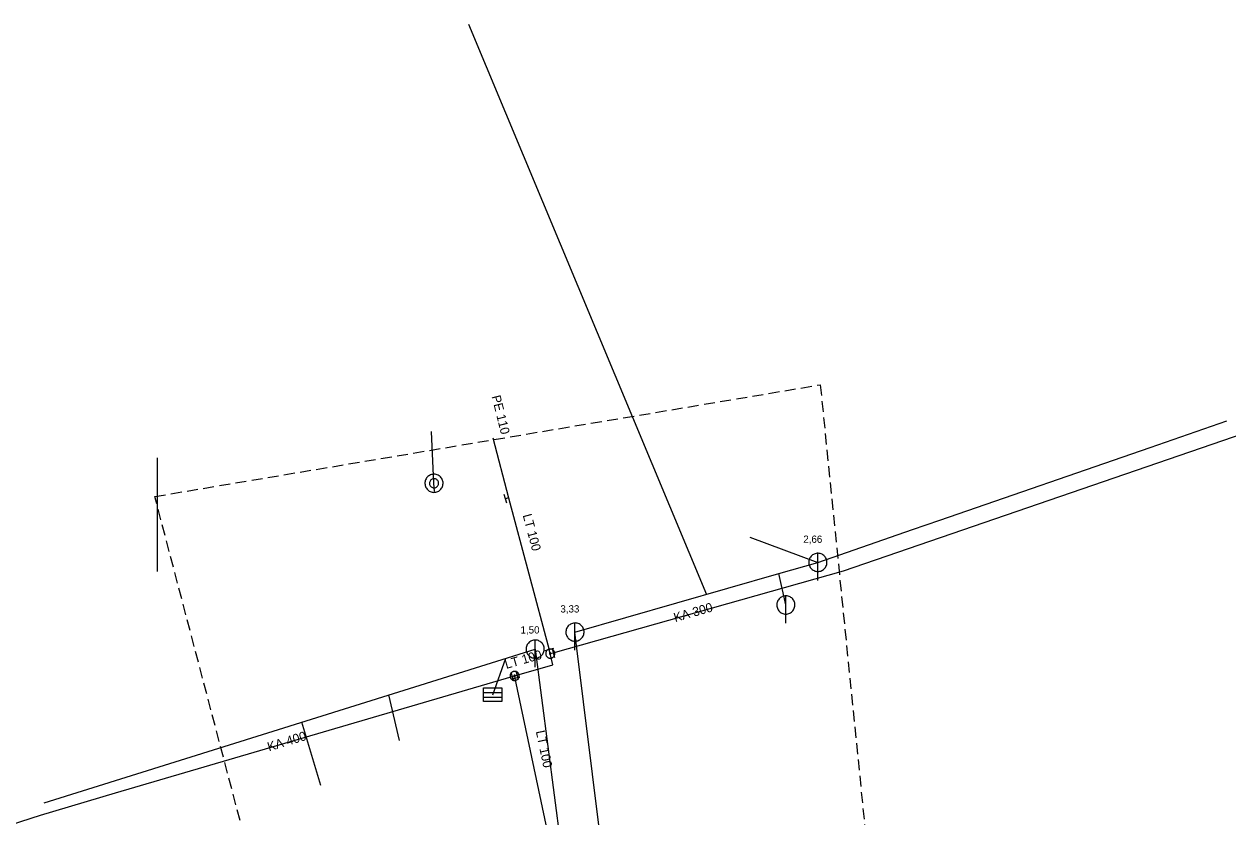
# Model space of a CAD drawing. Extents: x -689820 to -689363, y -975369 to -975062.
# Drawn here: x -689676.5 to -689544.2, y -975149.6 to -975062.5 of the extents above; entities that cross this region are included whole.
import ezdxf

# ---------------------------------------------------------------- set-up
doc = ezdxf.new("R2010")
doc.units = 0
doc.header["$LTSCALE"] = 0.4
doc.linetypes.add('MEDIUM_DASHED', pattern=[4.5, 3, -1.5])
doc.layers.add('1', color=7, linetype='Continuous')
for name, color, linetype, lineweight in [('11', 7, 'Continuous', 13), ('14', 7, 'Continuous', 25), ('17', 7, 'Continuous', 25), ('22', 7, 'Continuous', 13), ('34', 7, 'Continuous', 13), ('47', 7, 'Continuous', 13), ('63', 7, 'MEDIUM_DASHED', 25)]:
    doc.layers.add(name, color=color, linetype=linetype, lineweight=lineweight)

msp = doc.modelspace()

# ---------------------------------------------------------------- linework, layer by layer
at = {"layer": '11'}
for p, q in [((-689627.632, -975062.464), (-689601.514, -975125.167)), ((-689631.44, -975112.952), (-689631.719, -975107.264)), ((-689661.83, -975122.655), (-689661.83, -975110.164)), ((-689631.384, -975113.844), (-689631.44, -975112.952)), ((-689596.725, -975118.868), (-689589.26, -975121.649)), ((-689592.78, -975126.329), (-689593.565, -975122.886)), ((-689624.972, -975136.205), (-689623.543, -975132.188)), ((-689635.232, -975141.223), (-689636.395, -975136.218)), ((-689643.875, -975146.186), (-689645.974, -975139.223))]:
    msp.add_line(p, q, dxfattribs=at)
at = {"layer": '14', "lineweight": 13}
for p, q in [((-689623.257, -975114.555), (-689623.579, -975114.66)), ((-689618.668, -975131.679), (-689618.789, -975131.26)), ((-689618.668, -975131.679), (-689618.329, -975131.609)), ((-689622.587, -975134.128), (-689622.51, -975134.399))]:
    msp.add_line(p, q, dxfattribs=at)
at = {"layer": '14'}
for p, q in [((-689609.76, -975179.3), (-689615.949, -975129.309)), ((-689674.28, -975148.101), (-689620.329, -975131.18)), ((-689620.329, -975131.18), (-689613.954, -975179.785))]:
    msp.add_line(p, q, dxfattribs=at)
for points in [[(-689589.26, -975121.649), (-689578.848, -975118.046), (-689575.848, -975117.009), (-689552.767, -975109.022), (-689544.32, -975106.1)], [(-689615.949, -975129.309), (-689593.565, -975122.886), (-689589.26, -975121.649)]]:
    msp.add_lwpolyline(points, dxfattribs=at)
at = {"layer": '14', "lineweight": 13}
msp.add_lwpolyline([(-689622.85, -975134.205), (-689622.587, -975134.128), (-689622.32, -975134.05)], dxfattribs=at)
at = {"layer": '17'}
for points in [[(-689618.329, -975131.609), (-689586.448, -975122.573), (-689510.214, -975096.362), (-689500.742, -975093.538)], [(-689624.98, -975107.969), (-689623.257, -975114.555), (-689618.789, -975131.26)], [(-689622.32, -975134.05), (-689618.366, -975132.898), (-689618.668, -975131.679)], [(-689742.145, -975169.096), (-689736.511, -975167.526), (-689719.508, -975163.375), (-689716.769, -975162.653), (-689711.482, -975161.26), (-689710.52, -975160.971), (-689674.675, -975149.452), (-689666.449, -975146.987), (-689622.85, -975134.205)], [(-689614.585, -975177.62), (-689615.184, -975174.495), (-689618.58, -975153.313), (-689618.739, -975152.34), (-689619, -975151.02), (-689622.51, -975134.399)]]:
    msp.add_lwpolyline(points, dxfattribs=at)
at = {"layer": '22'}
for p, q in [((-689589.26, -975123.649), (-689589.259, -975120.649)), ((-689592.78, -975128.329), (-689592.779, -975125.329)), ((-689615.949, -975131.309), (-689615.948, -975128.309)), ((-689620.329, -975133.18), (-689620.328, -975130.18)), ((-689625.983, -975135.948), (-689623.983, -975135.948)), ((-689625.983, -975136.448), (-689623.983, -975136.448))]:
    msp.add_line(p, q, dxfattribs=at)
for points in [[(-689630.44, -975112.952), (-689630.446, -975112.843), (-689630.463, -975112.735), (-689630.494, -975112.629), (-689630.534, -975112.528), (-689630.585, -975112.431), (-689630.647, -975112.341), (-689630.72, -975112.258), (-689630.799, -975112.184), (-689630.887, -975112.118), (-689630.982, -975112.063), (-689631.081, -975112.018), (-689631.186, -975111.985), (-689631.294, -975111.963), (-689631.402, -975111.953), (-689631.512, -975111.955), (-689631.62, -975111.969), (-689631.727, -975111.994), (-689631.83, -975112.031), (-689631.928, -975112.08), (-689632.021, -975112.138), (-689632.107, -975112.207), (-689632.183, -975112.284), (-689632.252, -975112.37), (-689632.311, -975112.462), (-689632.36, -975112.56), (-689632.397, -975112.663), (-689632.423, -975112.77), (-689632.436, -975112.878), (-689632.438, -975112.988), (-689632.428, -975113.097), (-689632.407, -975113.204), (-689632.374, -975113.308), (-689632.33, -975113.408), (-689632.274, -975113.503), (-689632.208, -975113.591), (-689632.134, -975113.671), (-689632.051, -975113.743), (-689631.962, -975113.805), (-689631.865, -975113.857), (-689631.764, -975113.898), (-689631.659, -975113.928), (-689631.551, -975113.946), (-689631.441, -975113.952), (-689631.331, -975113.946), (-689631.223, -975113.928), (-689631.119, -975113.899), (-689631.017, -975113.858), (-689630.919, -975113.806), (-689630.83, -975113.744), (-689630.747, -975113.673), (-689630.671, -975113.593), (-689630.607, -975113.505), (-689630.551, -975113.411), (-689630.507, -975113.311), (-689630.473, -975113.207), (-689630.451, -975113.099), (-689630.441, -975112.99)], [(-689630.94, -975112.952), (-689630.946, -975112.875), (-689630.963, -975112.8), (-689630.992, -975112.728), (-689631.032, -975112.662), (-689631.083, -975112.602), (-689631.141, -975112.551), (-689631.205, -975112.51), (-689631.277, -975112.479), (-689631.352, -975112.46), (-689631.428, -975112.452), (-689631.507, -975112.456), (-689631.581, -975112.473), (-689631.654, -975112.5), (-689631.722, -975112.539), (-689631.781, -975112.587), (-689631.833, -975112.645), (-689631.877, -975112.709), (-689631.909, -975112.779), (-689631.929, -975112.854), (-689631.94, -975112.931), (-689631.936, -975113.008), (-689631.921, -975113.084), (-689631.896, -975113.157), (-689631.858, -975113.225), (-689631.811, -975113.286), (-689631.755, -975113.34), (-689631.691, -975113.384), (-689631.622, -975113.418), (-689631.548, -975113.44), (-689631.472, -975113.451), (-689631.394, -975113.45), (-689631.318, -975113.437), (-689631.245, -975113.412), (-689631.176, -975113.377), (-689631.114, -975113.331), (-689631.058, -975113.276), (-689631.014, -975113.213), (-689630.977, -975113.144), (-689630.953, -975113.071), (-689630.941, -975112.994)], [(-689588.26, -975121.649), (-689588.265, -975121.54), (-689588.283, -975121.432), (-689588.313, -975121.326), (-689588.353, -975121.225), (-689588.405, -975121.128), (-689588.467, -975121.038), (-689588.539, -975120.955), (-689588.619, -975120.881), (-689588.707, -975120.815), (-689588.801, -975120.76), (-689588.901, -975120.715), (-689589.006, -975120.682), (-689589.113, -975120.66), (-689589.222, -975120.65), (-689589.332, -975120.652), (-689589.44, -975120.666), (-689589.547, -975120.691), (-689589.65, -975120.728), (-689589.748, -975120.777), (-689589.84, -975120.835), (-689589.926, -975120.904), (-689590.003, -975120.981), (-689590.072, -975121.067), (-689590.131, -975121.159), (-689590.179, -975121.257), (-689590.216, -975121.36), (-689590.242, -975121.467), (-689590.256, -975121.575), (-689590.259, -975121.685), (-689590.249, -975121.794), (-689590.228, -975121.901), (-689590.194, -975122.005), (-689590.15, -975122.105), (-689590.095, -975122.2), (-689590.029, -975122.288), (-689589.955, -975122.368), (-689589.872, -975122.44), (-689589.782, -975122.502), (-689589.686, -975122.554), (-689589.584, -975122.595), (-689589.479, -975122.625), (-689589.371, -975122.643), (-689589.261, -975122.649), (-689589.152, -975122.643), (-689589.044, -975122.625), (-689588.939, -975122.596), (-689588.837, -975122.555), (-689588.74, -975122.503), (-689588.65, -975122.441), (-689588.567, -975122.37), (-689588.492, -975122.29), (-689588.427, -975122.202), (-689588.371, -975122.108), (-689588.327, -975122.008), (-689588.293, -975121.904), (-689588.271, -975121.796), (-689588.261, -975121.687)], [(-689591.78, -975126.329), (-689591.785, -975126.22), (-689591.803, -975126.112), (-689591.833, -975126.006), (-689591.873, -975125.905), (-689591.925, -975125.808), (-689591.987, -975125.718), (-689592.059, -975125.635), (-689592.139, -975125.561), (-689592.227, -975125.495), (-689592.321, -975125.44), (-689592.421, -975125.395), (-689592.526, -975125.362), (-689592.633, -975125.34), (-689592.742, -975125.33), (-689592.852, -975125.332), (-689592.96, -975125.346), (-689593.067, -975125.371), (-689593.17, -975125.408), (-689593.268, -975125.457), (-689593.36, -975125.515), (-689593.446, -975125.584), (-689593.523, -975125.661), (-689593.592, -975125.747), (-689593.651, -975125.839), (-689593.699, -975125.937), (-689593.736, -975126.04), (-689593.762, -975126.147), (-689593.776, -975126.255), (-689593.779, -975126.365), (-689593.769, -975126.474), (-689593.748, -975126.581), (-689593.714, -975126.685), (-689593.67, -975126.785), (-689593.615, -975126.88), (-689593.549, -975126.968), (-689593.475, -975127.048), (-689593.392, -975127.12), (-689593.302, -975127.182), (-689593.206, -975127.234), (-689593.104, -975127.275), (-689592.999, -975127.305), (-689592.891, -975127.323), (-689592.781, -975127.329), (-689592.672, -975127.323), (-689592.564, -975127.305), (-689592.459, -975127.276), (-689592.357, -975127.235), (-689592.26, -975127.183), (-689592.17, -975127.121), (-689592.087, -975127.05), (-689592.012, -975126.97), (-689591.947, -975126.882), (-689591.891, -975126.788), (-689591.847, -975126.688), (-689591.813, -975126.584), (-689591.791, -975126.476), (-689591.781, -975126.367)], [(-689614.949, -975129.309), (-689614.954, -975129.2), (-689614.972, -975129.092), (-689615.002, -975128.986), (-689615.042, -975128.885), (-689615.094, -975128.788), (-689615.156, -975128.698), (-689615.228, -975128.615), (-689615.308, -975128.541), (-689615.396, -975128.475), (-689615.49, -975128.42), (-689615.59, -975128.375), (-689615.695, -975128.342), (-689615.802, -975128.32), (-689615.911, -975128.31), (-689616.021, -975128.312), (-689616.129, -975128.326), (-689616.236, -975128.351), (-689616.339, -975128.388), (-689616.437, -975128.437), (-689616.529, -975128.495), (-689616.615, -975128.564), (-689616.692, -975128.641), (-689616.761, -975128.727), (-689616.82, -975128.819), (-689616.868, -975128.917), (-689616.905, -975129.02), (-689616.931, -975129.127), (-689616.945, -975129.235), (-689616.948, -975129.345), (-689616.938, -975129.454), (-689616.917, -975129.561), (-689616.883, -975129.665), (-689616.839, -975129.765), (-689616.784, -975129.86), (-689616.718, -975129.948), (-689616.644, -975130.028), (-689616.561, -975130.1), (-689616.471, -975130.162), (-689616.375, -975130.214), (-689616.273, -975130.255), (-689616.168, -975130.285), (-689616.06, -975130.303), (-689615.95, -975130.309), (-689615.841, -975130.303), (-689615.733, -975130.285), (-689615.628, -975130.256), (-689615.526, -975130.215), (-689615.429, -975130.163), (-689615.339, -975130.101), (-689615.256, -975130.03), (-689615.181, -975129.95), (-689615.116, -975129.862), (-689615.06, -975129.768), (-689615.016, -975129.668), (-689614.982, -975129.564), (-689614.96, -975129.456), (-689614.95, -975129.347)], [(-689619.329, -975131.18), (-689619.334, -975131.071), (-689619.352, -975130.963), (-689619.382, -975130.857), (-689619.422, -975130.756), (-689619.474, -975130.659), (-689619.536, -975130.569), (-689619.608, -975130.486), (-689619.688, -975130.412), (-689619.776, -975130.346), (-689619.87, -975130.291), (-689619.97, -975130.246), (-689620.075, -975130.213), (-689620.182, -975130.191), (-689620.291, -975130.181), (-689620.401, -975130.183), (-689620.509, -975130.197), (-689620.616, -975130.222), (-689620.719, -975130.259), (-689620.817, -975130.308), (-689620.909, -975130.366), (-689620.995, -975130.435), (-689621.072, -975130.512), (-689621.141, -975130.598), (-689621.2, -975130.69), (-689621.248, -975130.788), (-689621.285, -975130.891), (-689621.311, -975130.998), (-689621.325, -975131.106), (-689621.328, -975131.216), (-689621.318, -975131.325), (-689621.297, -975131.432), (-689621.263, -975131.536), (-689621.219, -975131.636), (-689621.164, -975131.731), (-689621.098, -975131.819), (-689621.024, -975131.899), (-689620.941, -975131.971), (-689620.851, -975132.033), (-689620.755, -975132.085), (-689620.653, -975132.126), (-689620.548, -975132.156), (-689620.44, -975132.174), (-689620.33, -975132.18), (-689620.221, -975132.174), (-689620.113, -975132.156), (-689620.008, -975132.127), (-689619.906, -975132.086), (-689619.809, -975132.034), (-689619.719, -975131.972), (-689619.636, -975131.901), (-689619.561, -975131.821), (-689619.496, -975131.733), (-689619.44, -975131.639), (-689619.396, -975131.539), (-689619.362, -975131.435), (-689619.34, -975131.327), (-689619.33, -975131.218)], [(-689625.983, -975135.448), (-689623.983, -975135.448), (-689623.983, -975136.948), (-689625.983, -975136.948)]]:
    msp.add_lwpolyline(points, close=True, dxfattribs=at)
at = {"layer": '34'}
for p, q in [((-689623.423, -975115.135), (-689623.733, -975114.184)), ((-689618.306, -975131.13), (-689619.272, -975131.388)), ((-689618.465, -975131.128), (-689618.193, -975132.09)), ((-689622.991, -975133.725), (-689622.709, -975134.684)), ((-689622.46, -975133.57), (-689622.18, -975134.53)), ((-689622.02, -975134.296), (-689622.999, -975134.5))]:
    msp.add_line(p, q, dxfattribs=at)
at = {"layer": '47'}
for points in [[(-689618.19, -975131.531), (-689618.208, -975131.483), (-689618.231, -975131.435), (-689618.259, -975131.392), (-689618.29, -975131.35), (-689618.327, -975131.312), (-689618.368, -975131.279), (-689618.411, -975131.25), (-689618.457, -975131.226), (-689618.505, -975131.206), (-689618.556, -975131.191), (-689618.608, -975131.182), (-689618.66, -975131.179), (-689618.712, -975131.181), (-689618.764, -975131.188), (-689618.815, -975131.201), (-689618.863, -975131.219), (-689618.911, -975131.242), (-689618.955, -975131.27), (-689618.996, -975131.301), (-689619.034, -975131.338), (-689619.067, -975131.379), (-689619.097, -975131.422), (-689619.121, -975131.469), (-689619.141, -975131.517), (-689619.155, -975131.567), (-689619.164, -975131.619), (-689619.168, -975131.671), (-689619.165, -975131.723), (-689619.158, -975131.775), (-689619.145, -975131.826), (-689619.127, -975131.874), (-689619.104, -975131.922), (-689619.077, -975131.967), (-689619.045, -975132.007), (-689619.008, -975132.045), (-689618.968, -975132.079), (-689618.925, -975132.108), (-689618.878, -975132.133), (-689618.829, -975132.152), (-689618.779, -975132.166), (-689618.727, -975132.175), (-689618.676, -975132.179), (-689618.623, -975132.176), (-689618.571, -975132.169), (-689618.52, -975132.156), (-689618.472, -975132.138), (-689618.424, -975132.115), (-689618.38, -975132.088), (-689618.339, -975132.056), (-689618.301, -975132.019), (-689618.267, -975131.979), (-689618.239, -975131.936), (-689618.214, -975131.89), (-689618.195, -975131.841), (-689618.18, -975131.79), (-689618.171, -975131.738), (-689618.168, -975131.687), (-689618.17, -975131.634), (-689618.177, -975131.582)], [(-689618.589, -975131.654), (-689618.592, -975131.646), (-689618.596, -975131.639), (-689618.6, -975131.632), (-689618.606, -975131.625), (-689618.612, -975131.618), (-689618.619, -975131.613), (-689618.625, -975131.608), (-689618.633, -975131.604), (-689618.641, -975131.601), (-689618.649, -975131.599), (-689618.658, -975131.597), (-689618.667, -975131.597), (-689618.675, -975131.597), (-689618.683, -975131.597), (-689618.692, -975131.6), (-689618.7, -975131.603), (-689618.707, -975131.607), (-689618.714, -975131.611), (-689618.721, -975131.617), (-689618.728, -975131.623), (-689618.733, -975131.63), (-689618.738, -975131.636), (-689618.742, -975131.644), (-689618.746, -975131.652), (-689618.747, -975131.66), (-689618.749, -975131.669), (-689618.749, -975131.678), (-689618.749, -975131.686), (-689618.749, -975131.694), (-689618.746, -975131.703), (-689618.743, -975131.711), (-689618.739, -975131.718), (-689618.735, -975131.725), (-689618.729, -975131.732), (-689618.723, -975131.739), (-689618.717, -975131.744), (-689618.71, -975131.749), (-689618.702, -975131.753), (-689618.694, -975131.757), (-689618.686, -975131.758), (-689618.677, -975131.76), (-689618.668, -975131.76), (-689618.66, -975131.76), (-689618.652, -975131.76), (-689618.643, -975131.757), (-689618.635, -975131.754), (-689618.628, -975131.75), (-689618.621, -975131.746), (-689618.614, -975131.74), (-689618.607, -975131.734), (-689618.602, -975131.728), (-689618.597, -975131.721), (-689618.593, -975131.713), (-689618.59, -975131.705), (-689618.588, -975131.697), (-689618.586, -975131.688), (-689618.586, -975131.679), (-689618.586, -975131.671), (-689618.586, -975131.663)], [(-689622.107, -975133.987), (-689622.124, -975133.938), (-689622.146, -975133.89), (-689622.174, -975133.846), (-689622.205, -975133.804), (-689622.241, -975133.766), (-689622.281, -975133.732), (-689622.324, -975133.703), (-689622.37, -975133.678), (-689622.418, -975133.657), (-689622.468, -975133.642), (-689622.52, -975133.632), (-689622.572, -975133.628), (-689622.624, -975133.629), (-689622.676, -975133.636), (-689622.727, -975133.648), (-689622.776, -975133.665), (-689622.824, -975133.687), (-689622.869, -975133.715), (-689622.91, -975133.746), (-689622.948, -975133.782), (-689622.982, -975133.822), (-689623.012, -975133.866), (-689623.037, -975133.912), (-689623.058, -975133.959), (-689623.072, -975134.009), (-689623.082, -975134.061), (-689623.087, -975134.114), (-689623.085, -975134.165), (-689623.078, -975134.217), (-689623.066, -975134.268), (-689623.049, -975134.317), (-689623.027, -975134.365), (-689623, -975134.41), (-689622.968, -975134.451), (-689622.932, -975134.489), (-689622.892, -975134.524), (-689622.849, -975134.554), (-689622.803, -975134.579), (-689622.755, -975134.599), (-689622.705, -975134.613), (-689622.653, -975134.623), (-689622.601, -975134.628), (-689622.549, -975134.626), (-689622.497, -975134.619), (-689622.446, -975134.607), (-689622.397, -975134.59), (-689622.349, -975134.568), (-689622.305, -975134.541), (-689622.263, -975134.509), (-689622.225, -975134.473), (-689622.19, -975134.433), (-689622.161, -975134.391), (-689622.136, -975134.345), (-689622.116, -975134.296), (-689622.101, -975134.246), (-689622.091, -975134.194), (-689622.087, -975134.143), (-689622.088, -975134.09), (-689622.095, -975134.038)], [(-689622.508, -975134.104), (-689622.51, -975134.096), (-689622.515, -975134.089), (-689622.519, -975134.082), (-689622.524, -975134.075), (-689622.53, -975134.068), (-689622.537, -975134.063), (-689622.543, -975134.058), (-689622.551, -975134.053), (-689622.559, -975134.051), (-689622.567, -975134.048), (-689622.576, -975134.046), (-689622.584, -975134.046), (-689622.593, -975134.046), (-689622.601, -975134.046), (-689622.61, -975134.049), (-689622.618, -975134.051), (-689622.625, -975134.056), (-689622.632, -975134.06), (-689622.639, -975134.065), (-689622.646, -975134.071), (-689622.651, -975134.078), (-689622.656, -975134.084), (-689622.661, -975134.092), (-689622.664, -975134.1), (-689622.666, -975134.108), (-689622.668, -975134.117), (-689622.668, -975134.125), (-689622.668, -975134.134), (-689622.668, -975134.142), (-689622.665, -975134.151), (-689622.663, -975134.159), (-689622.658, -975134.166), (-689622.654, -975134.173), (-689622.649, -975134.18), (-689622.643, -975134.187), (-689622.637, -975134.192), (-689622.63, -975134.197), (-689622.622, -975134.202), (-689622.614, -975134.205), (-689622.606, -975134.207), (-689622.597, -975134.209), (-689622.589, -975134.209), (-689622.58, -975134.209), (-689622.572, -975134.209), (-689622.563, -975134.206), (-689622.555, -975134.204), (-689622.548, -975134.199), (-689622.541, -975134.195), (-689622.534, -975134.19), (-689622.527, -975134.184), (-689622.522, -975134.178), (-689622.517, -975134.171), (-689622.512, -975134.163), (-689622.51, -975134.155), (-689622.507, -975134.147), (-689622.505, -975134.138), (-689622.505, -975134.13), (-689622.505, -975134.121), (-689622.505, -975134.113)]]:
    msp.add_lwpolyline(points, close=True, dxfattribs=at)
at = {"layer": '63'}
msp.add_lwpolyline([(-689662.123, -975114.404), (-689588.993, -975102.123), (-689588.993, -975102.123), (-689580.62, -975185.301), (-689580.62, -975185.301), (-689519.213, -975267.921), (-689519.213, -975267.921), (-689394.167, -975240.009), (-689394.167, -975240.009), (-689384.677, -975282.435), (-689384.677, -975282.435), (-689764.282, -975341.609), (-689764.282, -975341.609), (-689752.559, -975296.95), (-689752.559, -975296.95), (-689602.391, -975253.965), (-689627.512, -975210.422), (-689603.508, -975253.965), (-689648.167, -975167.437), (-689648.167, -975167.437)], close=True, dxfattribs=at)

# ---------------------------------------------------------------- texts
at = {"layer": '1'}
for s, rotation, p in [('PE 110', 284, (-689625.121, -975103.399)), ('LT 100', 285, (-689621.702, -975116.462)), ('KA 300', 16, (-689604.94, -975128.216)), ('LT 100', 16, (-689623.498, -975133.367)), ('KA 400', 17, (-689649.572, -975142.431)), ('LT 100', 282, (-689620.26, -975140.227))]:
    msp.add_text(s, height=1, rotation=rotation, dxfattribs=at).set_placement(p)
for s, p in [('2,66', (-689590.859, -975119.497)), ('3,33', (-689617.549, -975127.157)), ('1,50', (-689621.93, -975129.468))]:
    msp.add_text(s, height=0.8, dxfattribs=at).set_placement(p)

doc.saveas('drawing.dxf')
